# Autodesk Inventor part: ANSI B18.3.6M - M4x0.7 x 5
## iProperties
Comments: To add or edit properties for Autodesk Inventor files, use iProperties.
Created: 2004-07
Part Number: ANSI B18.3.6M - M4x0.7 x 5
Vendor: Autodesk Inc.
Document SubType Name: Modeling
Designer: John Blackburn
Material: Default
Description: Forged Hexagon Socket Set Screw - Oval Point - Metric
Standard: ANSI B18.3.6M
Alert: To add or edit properties for Autodesk Inventor files, use iProperties.
Control State: 0
Master: False
Checked Out: False
Shininess: 64.0
Length Units: 11269
Angle Units: 11279
Time Units: 11290
Mass Units: 11283
Length Display Precision: 3
Angle Display Precision: 2
Compacted: True
EGR: 1
Density: 0.0
Volumn: 0.0
Area: 0.0
PropertySet Name: Model Information
Author: John Blackburn
Revision Number: 8
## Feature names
1. Body [Revolution]
2. Slot [Extrusion]
3. Chamfer1
